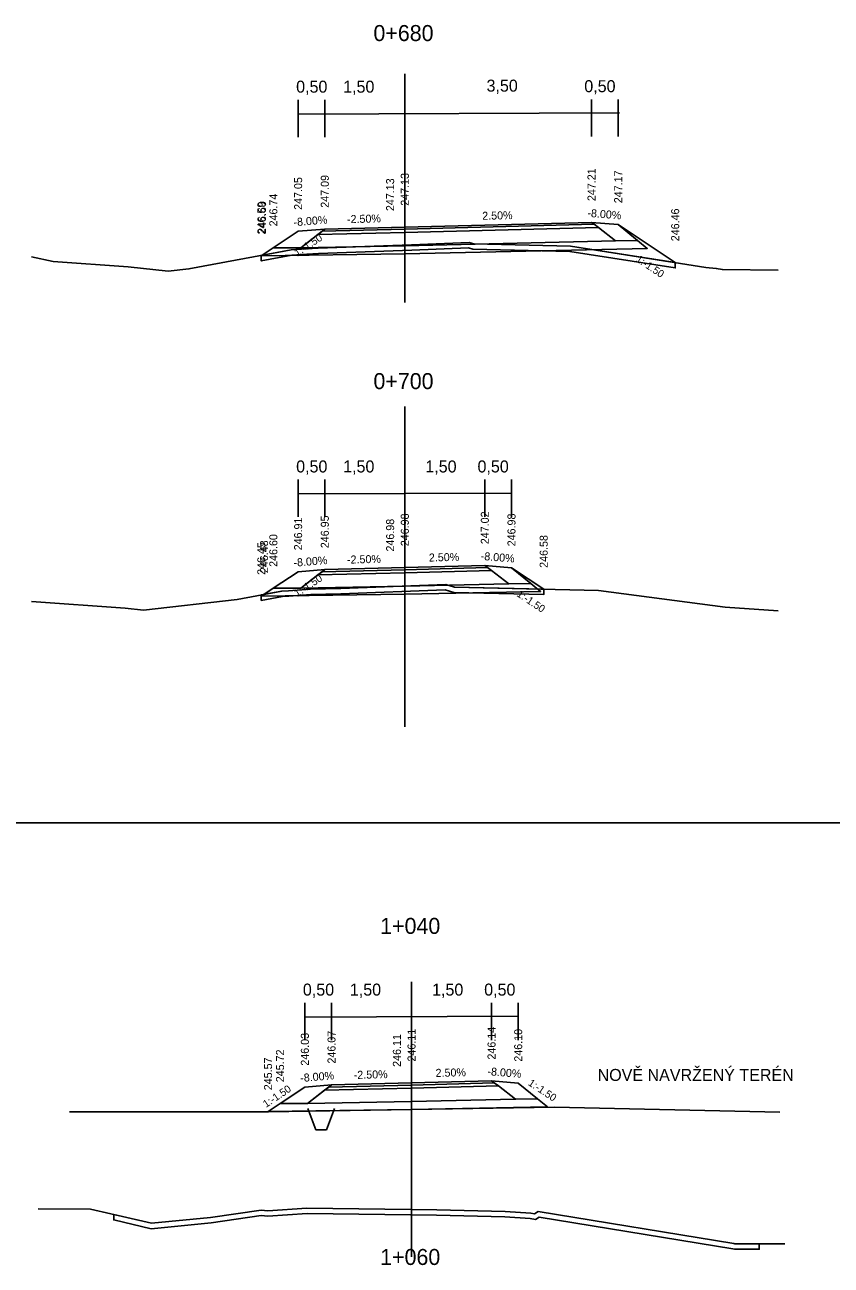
# Model space of a CAD drawing. Extents: x -552501 to -552394, y -1029983 to -1029892.
# Drawn here: x -552453.26 to -552438.15, y -1029961.04 to -1029937.8 of the extents above; entities that cross this region are included whole.
import ezdxf

# ---------------------------------------------------------------- set-up
doc = ezdxf.new("R2010")
doc.units = 0
for name, color, linetype in [('1', 7, 'Continuous'), ('16', 7, 'Continuous'), ('60', 7, 'Continuous'), ('9', 7, 'Continuous'), ('Implicitní', 7, 'Continuous'), ('rámeček', 7, 'Continuous')]:
    doc.layers.add(name, color=color, linetype=linetype)

msp = doc.modelspace()

# ---------------------------------------------------------------- linework, layer by layer
for p, q in [((-552448.693, -1029958.17), (-552452.429, -1029958.17)), ((-552447.81, -1029958.504), (-552447.96, -1029958.104)), ((-552447.61, -1029958.504), (-552447.46, -1029958.104)), ((-552447.81, -1029958.504), (-552447.61, -1029958.504))]:
    msp.add_line(p, q)
for points in [[(-552448.83, -1029942.128), (-552448.816, -1029942.119), (-552448.605, -1029941.978), (-552448.14, -1029941.668), (-552447.64, -1029941.628), (-552446.14, -1029941.591), (-552442.64, -1029941.503), (-552442.14, -1029941.543), (-552441.071, -1029942.256)], [(-552453.14, -1029942.149), (-552452.73, -1029942.236), (-552451.326, -1029942.336), (-552450.579, -1029942.419), (-552450.186, -1029942.374), (-552448.272, -1029942.018), (-552447.985, -1029941.999), (-552447.766, -1029941.984), (-552446.012, -1029941.923), (-552444.933, -1029941.881), (-552444.849, -1029941.907), (-552443.036, -1029941.949), (-552440.499, -1029942.345), (-552440.3, -1029942.366), (-552440.186, -1029942.386), (-552439.14, -1029942.395)], [(-552448.83, -1029948.507), (-552448.779, -1029948.474), (-552448.605, -1029948.357), (-552448.14, -1029948.047), (-552447.64, -1029948.007), (-552446.14, -1029947.97), (-552444.64, -1029947.932), (-552444.14, -1029947.972), (-552443.536, -1029948.375)], [(-552453.14, -1029948.603), (-552451.382, -1029948.729), (-552451.037, -1029948.767), (-552449.28, -1029948.567), (-552448.447, -1029948.412), (-552448.322, -1029948.404), (-552447.908, -1029948.374), (-552447.341, -1029948.365), (-552445.369, -1029948.287), (-552445.208, -1029948.336), (-552442.511, -1029948.399), (-552440.132, -1029948.71), (-552439.14, -1029948.783)], [(-552448.693, -1029958.17), (-552443.336, -1029958.08), (-552439.11, -1029958.177)], [(-552453.014, -1029959.982), (-552452.035, -1029959.99), (-552450.888, -1029960.256), (-552449.781, -1029960.15), (-552448.835, -1029960.011), (-552448.707, -1029960.024), (-552447.974, -1029959.974), (-552445.541, -1029960.003), (-552444.259, -1029960.038), (-552443.78, -1029960.065), (-552443.711, -1029960.077), (-552443.641, -1029960.037), (-552439.973, -1029960.637), (-552439.951, -1029960.64), (-552439.014, -1029960.642)]]:
    msp.add_lwpolyline(points)
for points in [[(-552446.14, -1029941.631), (-552447.691, -1029941.668), (-552447.768, -1029941.728), (-552446.14, -1029941.691), (-552442.512, -1029941.597), (-552442.589, -1029941.537), (-552446.14, -1029941.631), (-552442.589, -1029941.537), (-552442.64, -1029941.503), (-552446.14, -1029941.591), (-552447.64, -1029941.628), (-552447.691, -1029941.668)], [(-552442.64, -1029941.503), (-552442.14, -1029941.543), (-552441.779, -1029941.841), (-552442.19, -1029941.847), (-552442.512, -1029941.597), (-552442.589, -1029941.537)], [(-552447.64, -1029941.628), (-552448.14, -1029941.668), (-552448.605, -1029941.978), (-552448.09, -1029941.978)], [(-552448.09, -1029941.978), (-552447.768, -1029941.728), (-552446.14, -1029941.691), (-552442.512, -1029941.597), (-552442.19, -1029941.847), (-552446.14, -1029941.941)], [(-552447.768, -1029941.728), (-552447.691, -1029941.668), (-552446.14, -1029941.631), (-552442.589, -1029941.537), (-552442.512, -1029941.597), (-552446.14, -1029941.691)], [(-552448.83, -1029942.128), (-552448.605, -1029941.978), (-552448.09, -1029941.978), (-552446.14, -1029941.941), (-552442.19, -1029941.847), (-552441.779, -1029941.841), (-552441.594, -1029941.991), (-552446.14, -1029942.091)], [(-552448.83, -1029942.122), (-552448.272, -1029942.018), (-552447.985, -1029941.999), (-552447.766, -1029941.984), (-552446.012, -1029941.923), (-552444.933, -1029941.881), (-552444.849, -1029941.907), (-552443.036, -1029941.949), (-552441.071, -1029942.256), (-552441.071, -1029942.357), (-552443.044, -1029942.049), (-552444.864, -1029942.006), (-552444.945, -1029941.982), (-552446.008, -1029942.023), (-552447.761, -1029942.084), (-552447.978, -1029942.099), (-552448.26, -1029942.118), (-552448.83, -1029942.224)], [(-552447.64, -1029948.007), (-552448.14, -1029948.047), (-552448.605, -1029948.357), (-552448.09, -1029948.357)], [(-552446.14, -1029948.01), (-552447.691, -1029948.047), (-552447.768, -1029948.107), (-552446.14, -1029948.07), (-552444.512, -1029948.026), (-552444.589, -1029947.966), (-552446.14, -1029948.01), (-552444.589, -1029947.966), (-552444.64, -1029947.932), (-552446.14, -1029947.97), (-552447.64, -1029948.007), (-552447.691, -1029948.047)], [(-552447.768, -1029948.107), (-552447.691, -1029948.047), (-552446.14, -1029948.01), (-552444.589, -1029947.966), (-552444.512, -1029948.026), (-552446.14, -1029948.07)], [(-552444.64, -1029947.932), (-552444.14, -1029947.972), (-552443.779, -1029948.27), (-552444.19, -1029948.276), (-552444.512, -1029948.026), (-552444.589, -1029947.966)], [(-552448.09, -1029948.357), (-552447.768, -1029948.107), (-552446.14, -1029948.07), (-552444.512, -1029948.026), (-552444.19, -1029948.276), (-552446.14, -1029948.32)], [(-552448.83, -1029948.507), (-552448.605, -1029948.357), (-552448.09, -1029948.357), (-552446.14, -1029948.32), (-552444.19, -1029948.276), (-552443.779, -1029948.27), (-552443.594, -1029948.42), (-552446.14, -1029948.47)], [(-552448.83, -1029948.483), (-552448.447, -1029948.412), (-552448.322, -1029948.404), (-552447.908, -1029948.374), (-552447.341, -1029948.365), (-552445.369, -1029948.287), (-552445.208, -1029948.336), (-552443.536, -1029948.375), (-552443.536, -1029948.475), (-552445.223, -1029948.435), (-552445.381, -1029948.388), (-552447.338, -1029948.465), (-552447.904, -1029948.474), (-552448.315, -1029948.503), (-552448.434, -1029948.511), (-552448.83, -1029948.585)], [(-552447.514, -1029957.663), (-552448.014, -1029957.703), (-552448.479, -1029958.013), (-552447.965, -1029958.013)], [(-552447.965, -1029958.013), (-552447.643, -1029957.763), (-552446.015, -1029957.725), (-552444.386, -1029957.682), (-552444.064, -1029957.932), (-552446.015, -1029957.975)], [(-552446.015, -1029957.665), (-552447.565, -1029957.703), (-552447.643, -1029957.763), (-552446.015, -1029957.725), (-552444.386, -1029957.682), (-552444.463, -1029957.622), (-552446.015, -1029957.665), (-552444.463, -1029957.622), (-552444.514, -1029957.588), (-552446.014, -1029957.625), (-552447.514, -1029957.663), (-552447.565, -1029957.703)], [(-552447.643, -1029957.763), (-552447.565, -1029957.703), (-552446.015, -1029957.665), (-552444.463, -1029957.622), (-552444.386, -1029957.682), (-552446.015, -1029957.725)], [(-552444.514, -1029957.588), (-552444.014, -1029957.628), (-552443.653, -1029957.925), (-552444.064, -1029957.932), (-552444.386, -1029957.682), (-552444.463, -1029957.622)], [(-552448.704, -1029958.163), (-552448.479, -1029958.013), (-552447.965, -1029958.013), (-552446.015, -1029957.975), (-552444.064, -1029957.932), (-552443.653, -1029957.925), (-552443.468, -1029958.075), (-552446.015, -1029958.125)], [(-552451.597, -1029960.091), (-552450.888, -1029960.256), (-552449.781, -1029960.15), (-552448.835, -1029960.011), (-552448.707, -1029960.024), (-552447.974, -1029959.974), (-552445.541, -1029960.003), (-552444.259, -1029960.038), (-552443.78, -1029960.065), (-552443.711, -1029960.077), (-552443.641, -1029960.037), (-552439.973, -1029960.637), (-552439.951, -1029960.64), (-552439.494, -1029960.641), (-552439.494, -1029960.741), (-552439.959, -1029960.74), (-552439.989, -1029960.735), (-552443.622, -1029960.141), (-552443.692, -1029960.182), (-552443.792, -1029960.165), (-552444.263, -1029960.138), (-552445.543, -1029960.103), (-552447.972, -1029960.074), (-552448.709, -1029960.125), (-552448.833, -1029960.111), (-552449.769, -1029960.249), (-552450.894, -1029960.357), (-552451.597, -1029960.194)]]:
    msp.add_lwpolyline(points, close=True)
at = {"layer": '60'}
for p, q in [((-552446.14, -1029938.717), (-552446.14, -1029943.004)), ((-552446.14, -1029944.953), (-552446.14, -1029950.953)), ((-552446.014, -1029955.732), (-552446.014, -1029960.887))]:
    msp.add_line(p, q, dxfattribs=at)
at = {"layer": '9'}
for p, q in [((-552448.14, -1029939.207), (-552448.14, -1029939.904)), ((-552447.64, -1029939.207), (-552447.64, -1029939.904)), ((-552446.14, -1029939.207), (-552446.14, -1029940.707)), ((-552442.638, -1029939.198), (-552442.638, -1029939.895)), ((-552442.138, -1029939.198), (-552442.138, -1029939.895)), ((-552448.14, -1029946.323), (-552448.14, -1029947.02)), ((-552447.64, -1029946.323), (-552447.64, -1029947.02)), ((-552446.14, -1029946.323), (-552446.14, -1029947.823)), ((-552444.64, -1029946.323), (-552444.64, -1029947.02)), ((-552444.14, -1029946.323), (-552444.14, -1029947.02)), ((-552448.014, -1029956.125), (-552448.014, -1029956.823)), ((-552447.514, -1029956.125), (-552447.514, -1029956.823)), ((-552446.014, -1029956.125), (-552446.014, -1029957.625)), ((-552444.514, -1029956.125), (-552444.514, -1029956.823)), ((-552444.014, -1029956.125), (-552444.014, -1029956.823))]:
    msp.add_line(p, q, dxfattribs=at)
at = {"layer": 'Implicitní'}
for p, q in [((-552448.13, -1029939.474), (-552442.114, -1029939.448)), ((-552448.13, -1029946.59), (-552444.14, -1029946.573)), ((-552448.004, -1029956.393), (-552444.014, -1029956.375))]:
    msp.add_line(p, q, dxfattribs=at)
at = {"layer": 'rámeček'}
msp.add_line((-552499.755, -1029952.75), (-552394.755, -1029952.75), dxfattribs=at)
msp.add_line((-552499.755, -1029952.75), (-552394.755, -1029952.75), dxfattribs=at)
msp.add_line((-552499.755, -1029952.75), (-552394.755, -1029952.75), dxfattribs=at)

# ---------------------------------------------------------------- texts
for rotation, p in [(33.6902, (-552448.156, -1029942.148)), (326.3098, (-552441.822, -1029942.224)), (33.6902, (-552448.156, -1029948.527)), (326.3098, (-552444.054, -1029948.498)), (33.6902, (-552448.742, -1029958.095)), (326.3098, (-552443.841, -1029957.658))]:
    msp.add_text('1:-1.50', height=0.14, rotation=rotation).set_placement(p)
at = {"layer": '1'}
for s, p in [('0+680', (-552446.728, -1029938.105)), ('0+700', (-552446.728, -1029944.626)), ('1+040', (-552446.602, -1029954.834)), ('1+060', (-552446.602, -1029961.037))]:
    msp.add_text(s, height=0.3, dxfattribs=at).set_placement(p)
at = {"layer": '16'}
for s, p in [('0,50', (-552448.177, -1029939.072)), ('1,50', (-552447.296, -1029939.072)), ('3,50', (-552444.608, -1029939.053)), ('0,50', (-552442.775, -1029939.063)), ('0,50', (-552448.177, -1029946.188)), ('1,50', (-552447.296, -1029946.188)), ('1,50', (-552445.755, -1029946.188)), ('0,50', (-552444.777, -1029946.188)), ('0,50', (-552448.051, -1029955.99)), ('1,50', (-552447.17, -1029955.99)), ('1,50', (-552445.629, -1029955.99)), ('0,50', (-552444.652, -1029955.99)), ('NOVĚ NAVRŽENÝ TERÉN', (-552442.526, -1029957.589))]:
    msp.add_text(s, height=0.225, dxfattribs=at).set_placement(p)
for s, rotation, p in [('247.21', 90, (-552442.565, -1029941.103)), ('247.17', 90, (-552442.065, -1029941.143)), ('247.05', 90, (-552448.065, -1029941.268)), ('247.09', 90, (-552447.565, -1029941.228)), ('247.13', 90, (-552446.34, -1029941.291)), ('247.13', 90, (-552446.065, -1029941.191)), ('246.74', 90, (-552448.53, -1029941.578)), ('246.59', 90, (-552448.755, -1029941.728)), ('246.60', 90, (-552448.741, -1029941.719)), ('-8.00%', 355.4261, (-552442.721, -1029941.397)), ('246.46', 90, (-552440.996, -1029941.856)), ('-8.00%', 4.5739, (-552448.221, -1029941.575)), ('-2.50%', 1.4321, (-552447.222, -1029941.518)), ('2.50%', 1.4321, (-552444.687, -1029941.455)), ('246.91', 90, (-552448.065, -1029947.647)), ('246.95', 90, (-552447.565, -1029947.607)), ('246.98', 90, (-552446.34, -1029947.67)), ('246.98', 90, (-552446.065, -1029947.57)), ('247.02', 90, (-552444.565, -1029947.532)), ('246.98', 90, (-552444.065, -1029947.572)), ('246.45', 90, (-552448.755, -1029948.107)), ('246.48', 90, (-552448.704, -1029948.074)), ('246.60', 90, (-552448.53, -1029947.957)), ('246.58', 90, (-552443.461, -1029947.975)), ('-8.00%', 4.5739, (-552448.221, -1029947.954)), ('-2.50%', 1.4321, (-552447.222, -1029947.897)), ('2.50%', 1.4321, (-552445.687, -1029947.858)), ('-8.00%', 355.4261, (-552444.721, -1029947.826)), ('246.14', 90, (-552444.439, -1029957.188)), ('246.03', 90, (-552447.939, -1029957.303)), ('246.07', 90, (-552447.439, -1029957.263)), ('246.11', 90, (-552446.214, -1029957.325)), ('246.11', 90, (-552445.939, -1029957.225)), ('246.10', 90, (-552443.939, -1029957.228)), ('245.72', 90, (-552448.404, -1029957.613)), ('245.57', 90, (-552448.629, -1029957.763)), ('-8.00%', 4.5739, (-552448.095, -1029957.609)), ('-2.50%', 1.4321, (-552447.096, -1029957.552)), ('2.50%', 1.4321, (-552445.561, -1029957.514)), ('-8.00%', 355.4261, (-552444.595, -1029957.481))]:
    msp.add_text(s, height=0.15, rotation=rotation, dxfattribs=at).set_placement(p)

doc.saveas('drawing.dxf')
